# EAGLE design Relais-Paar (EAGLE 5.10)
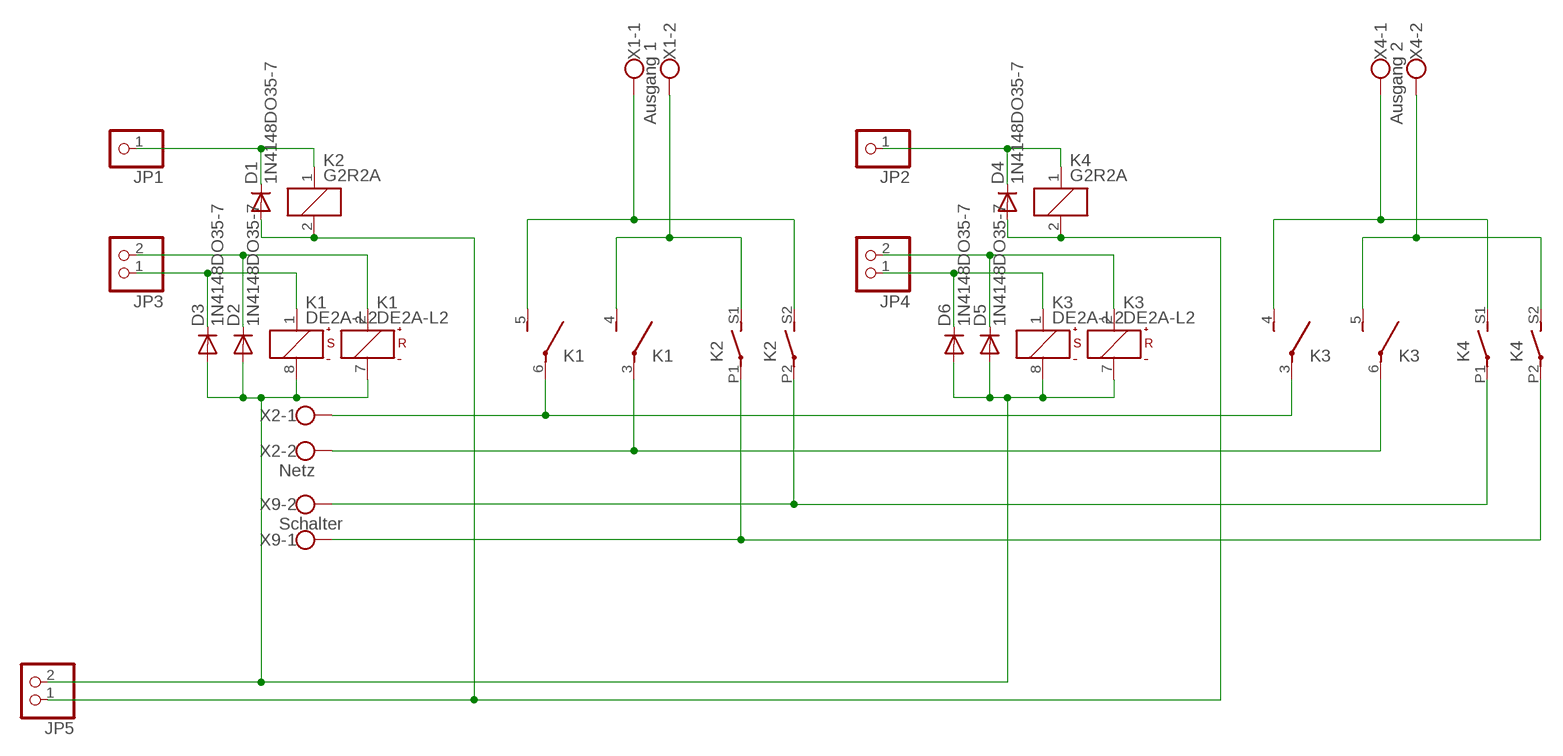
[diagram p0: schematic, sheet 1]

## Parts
D1  1N4148DO35-7  [DO35-7]
D2  1N4148DO35-7  [DO35-7]
D3  1N4148DO35-7  [DO35-7]
D4  1N4148DO35-7  [DO35-7]
D5  1N4148DO35-7  [DO35-7]
D6  1N4148DO35-7  [DO35-7]
JP1  PINHD-1X1  [1X01]
JP2  PINHD-1X1  [1X01]
JP3  PINHD-1X2  [1X02]
JP4  PINHD-1X2  [1X02]
JP5  PINHD-1X2  [1X02]
K1  DE2A-L2  [DE2A-L2]
K2  G2R2A  [G2R2A]
K3  DE2A-L2  [DE2A-L2]
K4  G2R2A  [G2R2A]
X1  Ausgang 1  W237-02P  [W237-132]
X2  Netz  W237-02P  [W237-132]
X4  Ausgang 2  W237-02P  [W237-132]
X9  Schalter  W237-02P  [W237-132]

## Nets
N$1 [mains]: K1.6(S2:P) K3.3(S1:P) X2.1
N$2 [mains]: K1.3(S1:P) K3.6(S2:P) X2.2
N$3 [mains]: K1.5(S2:S) K2.S2(3:S) X1.1
N$4 [mains]: K1.4(S1:S) K2.S1(2:S) X1.2
N$5 [mains]: K2.P1(2:P) K4.P2(3:P) X9.1
N$6 [mains]: K2.P2(3:P) K4.P1(2:P) X9.2
N$7: D2.A D3.A D5.A D6.A JP5.2 K1.7(R:-) K1.8(S:-) K3.7(R:-) K3.8(S:-)
N$8: D3.C JP3.1 K1.1(S:+)
N$9: D2.C JP3.2 K1.2(R:+)
N$10: D1.A D4.A JP5.1 K2.2 K4.2
N$11: D1.C JP1.1 K2.1
N$14 [mains]: K3.4(S1:S) K4.S1(2:S) X4.1
N$15 [mains]: K3.5(S2:S) K4.S2(3:S) X4.2
N$19: D6.C JP4.1 K3.1(S:+)
N$20: D5.C JP4.2 K3.2(R:+)
N$22: D4.C JP2.1 K4.1

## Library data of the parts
D1-D6 = diode:1N4148: DIODE
JP1 JP2 = pinhead:PINHD-1X1: PIN HEADER
JP3-JP5 = pinhead:PINHD-1X2: PIN HEADER
K1 K3 = 11my-mechanics:DE2A-L2*: MINIATURE RELAY NAiS DE2a-L2 Source: Pollin
K2 K4 = relay:G2R2A: RELAY 2 x norm. open, Omron
X1 X2 X4 X9 = con-wago-508:W237-02P: WAGO SREW CLAMP

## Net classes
1 mains: width 4 mm, clearance 2 mm

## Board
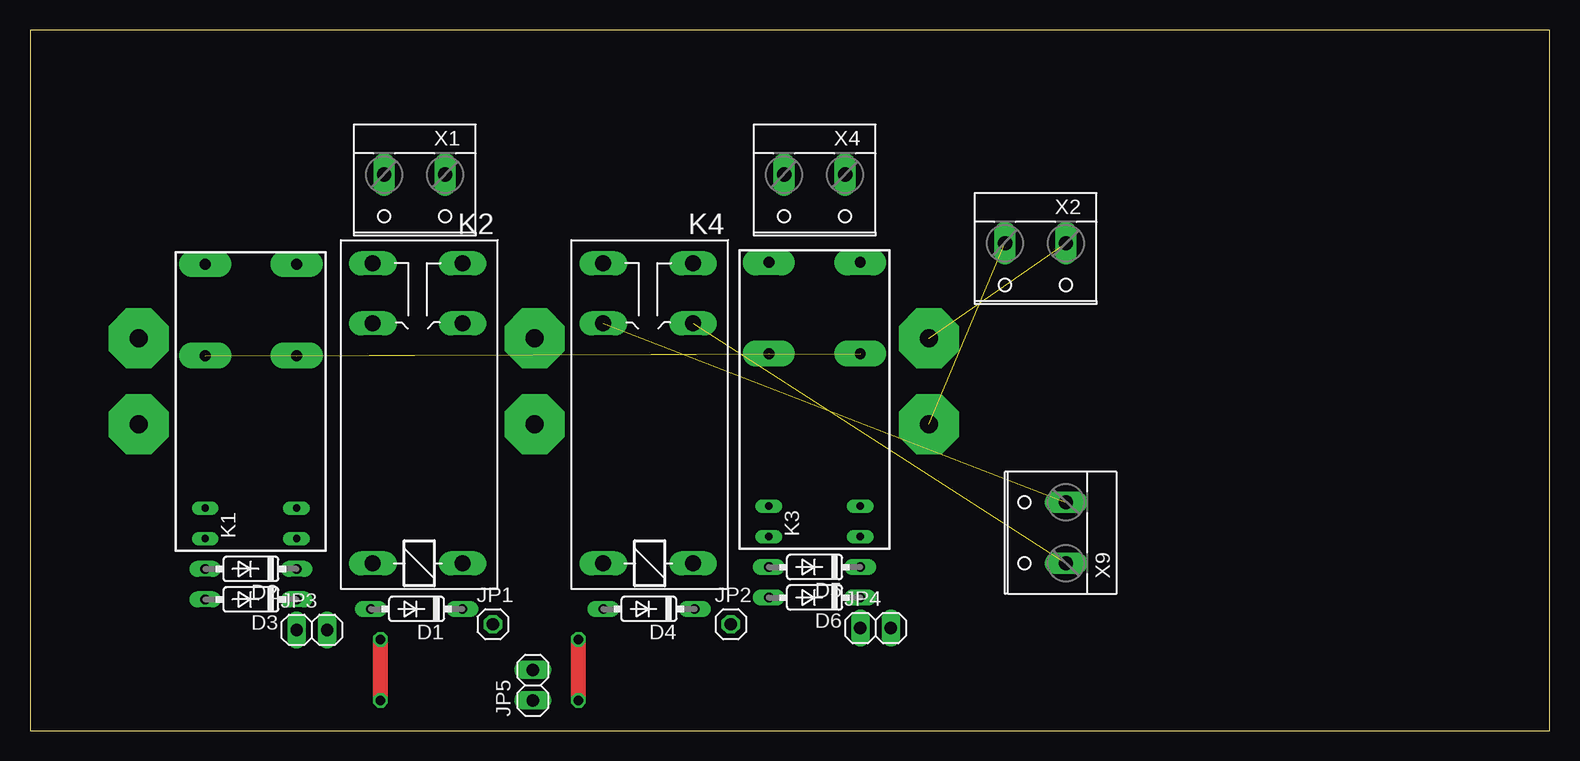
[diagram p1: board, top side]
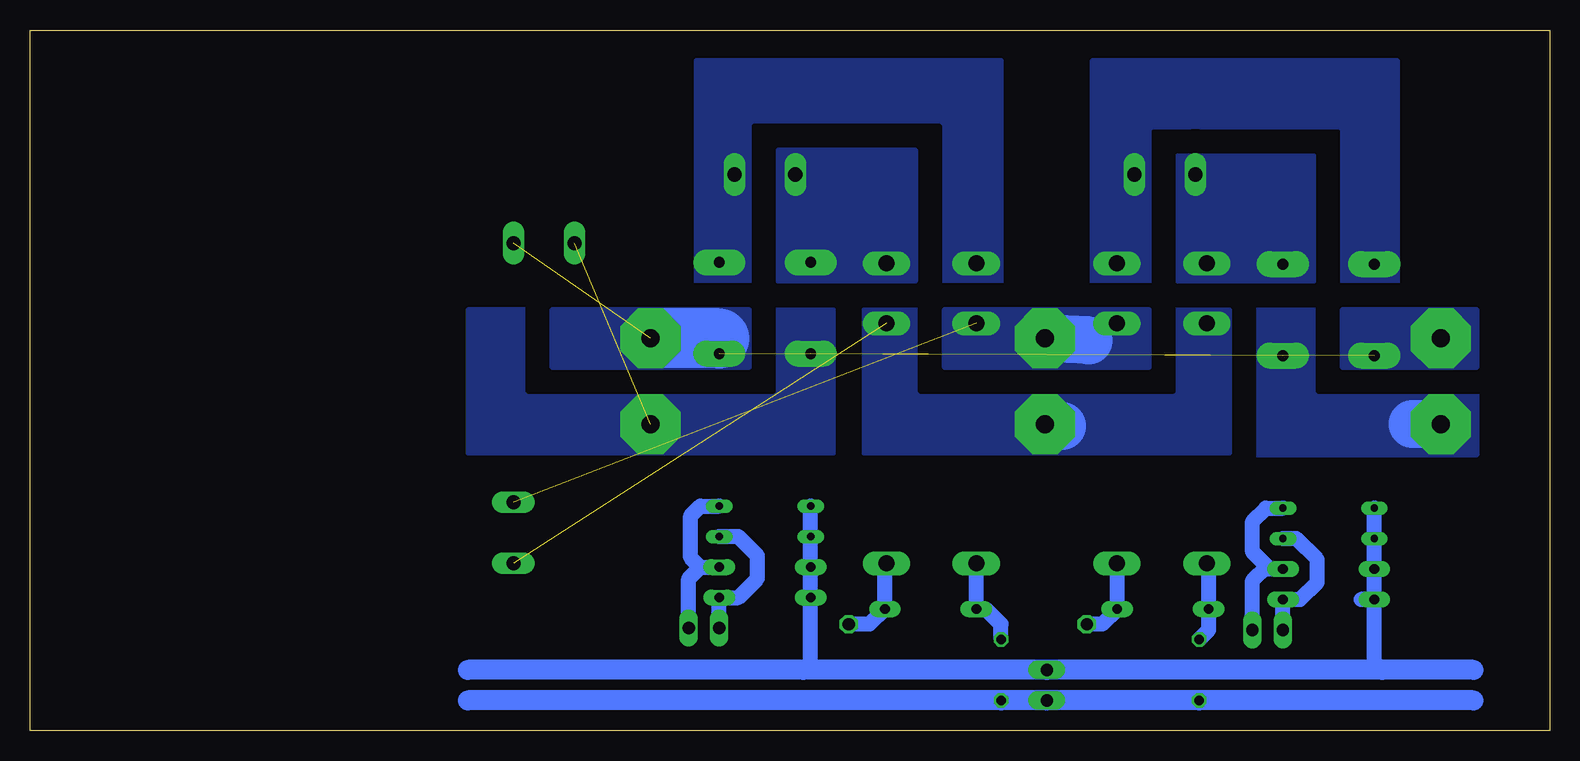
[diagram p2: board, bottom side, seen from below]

Size 126.67 x 58.41 mm. Coordinates in mm from the lower left corner, seen from the top.
Outline: 0,0 126.67,0 126.67,58.41 0,58.41 0,0
Copper layers (1*16): Top 0.035mm / dielectric 1.5mm / Bottom 0.035mm
Design rules "default": minimum track width 10mil, minimum drill 24mil, track to track 8mil, track to pad 8mil, pad to pad 8mil, via to via 8mil, smd to smd 8mil, copper to edge 40mil, drill to drill 8mil, minimum pad ring 10mil, minimum via ring 8mil, stop-mask expansion 4mil, vias tented up to drill 0mil, thermal gap 10mil

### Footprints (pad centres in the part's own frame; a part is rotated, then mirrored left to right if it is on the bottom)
DO35-7 = drill 0.813 long: A 3.81,0; C -3.81,0
1X01 = drill 1.016 octagon: 1 0,0
1X02 = drill 1.016 long: 1 -1.27,0; 2 1.27,0
DE2A-L2 = drill 0.61 long: 1 -8.89,-3.81; 2 -6.35,-3.81; 7 -6.35,3.81; 8 -8.89,3.81 | drill 0.9 pad 2.184 long: 3 6.35,-3.81; 4 13.97,-3.81; 5 13.97,3.81; 6 6.35,3.81
G2R2A = drill 1.321 long: 1 -2.54,-3.683; 2 -2.54,3.81; P1 17.45,3.81; P2 17.45,-3.683; S1 22.454,3.81; S2 22.454,-3.683
W237-132 = drill 1.194 long: 1 -2.54,-0.635; 2 2.54,-0.635

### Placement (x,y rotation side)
D1  32.23,10.16 180 top
D2  18.41,13.49 180 top
D3  18.41,10.95 180 top
D4  51.59,10.16 180 top
D5  65.41,13.65 180 top
D6  65.41,11.11 180 top
JP1  38.58,8.89 0 top
JP2  58.42,8.89 0 top
JP3  23.5,8.41 0 top
JP4  70.48,8.57 0 top
JP5  41.91,3.81 90 top
K1  18.41,24.92 90 top
K2  32.38,16.51 90 top
K3  65.41,25.08 90 top
K4  51.59,16.51 90 top
X1  32.07,45.72 180 top
X2  83.82,40.01 180 top
X4  65.41,45.72 180 top
X9  85.72,16.51 90 top

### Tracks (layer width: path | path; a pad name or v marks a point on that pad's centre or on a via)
N$1  (via drill 1.5 pad 5)  (2 unrouted)
  Bottom 5: 69.22,32.7 v74.93,32.7 | 69.22,32.7
  other vias: 9.05,32.7
  pour Bottom: 17.3,35.08 17.3,30.32 6.03,30.32 6.03,35.08
  pour Bottom (no thermals): 83.19,35.08 83.19,30.32 66.67,30.32 66.67,35.08
N$2  (via drill 1.5 pad 5)  (2 unrouted)
  Bottom 4: v9.05,25.56 11.43,25.56
  other vias: 74.93,25.56
  pour Bottom (isolate 2, rank 3): 24.61,35.08 24.61,23.02 6.03,23.02 6.03,35.08
  pour Bottom (isolate 2, rank 2, no thermals): 59.69,23.18 59.69,35.08 90.17,35.08 90.17,23.18
N$3
  pour Bottom (isolate 2, rank 4, no thermals): 12.7,36.83 38.1,36.83 38.1,55.88 12.7,55.88
N$4
  pour Bottom (no thermals): 19.69,47.94 19.69,37.47 30.96,37.47 30.96,47.94
N$5  (via drill 1.5 pad 5)  (1 unrouted)
  Bottom 4: v42.07,25.56 40.64,25.4
  pour Bottom (isolate 2, rank 2, no thermals): 26.67,23.18 26.67,35.08 57.15,35.08 57.15,23.18
N$6  (via drill 1.5 pad 5)  (1 unrouted)
  Bottom 4: 38.42,32.54 v42.07,32.7
  pour Bottom (no thermals): 50.48,35.08 50.48,30.32 33.34,30.32 33.34,35.08
N$7
  Bottom 1.27: K1.7 K1.8 D2.A D3.A | D3.A 15.72,10.95 | K3.8 K3.7 | D5.A D6.A 61.59,5.71 62.23,5.08 | D5.A | D5.A K3.8 | K3.8 | D3.A 14.61,5.71 13.97,5.08
  Bottom 1.676: 90.17,5.08 62.23,5.08 JP5.2 13.97,5.08 6.35,5.08
N$8
  Bottom 1.27: K1.1 | K1.1 21.11,16.03 19.37,14.29 19.37,12.38 20.8,10.95 D3.C | D3.C 21.59,10.95 | JP3.1 D3.C | D3.C
N$9
  Bottom 1.27: D2.C | D2.C 23.34,13.49 23.57,13.73 | 23.57,13.73 24.77,14.92 24.77,17.46 23.65,18.57 K1.2 | K1.2 | JP3.2 24.77,12.54 23.57,13.73
N$10  (via drill 0.8)
  Top 1.27: v45.72,2.54 v45.72,7.62 | v29.21,2.54 v29.21,7.62
  Bottom 1.27: K4.2 D4.A 46.99,10.16 45.72,8.89 v45.72,7.62 | K2.2 28.42,13.81 D1.A 28.42,8.41 v29.21,7.62
  Bottom 1.676: 90.17,2.54 v45.72,2.54 JP5.1 v29.21,2.54 6.35,2.54
N$11
  Bottom 1.27: K2.1 36.04,13.84 D1.C 37.31,8.89 JP1.1
N$14
  pour Bottom (isolate 2, rank 4, no thermals): 45.72,36.83 71.12,36.83 71.12,55.88 45.72,55.88
N$15
  pour Bottom (no thermals): 52.86,48.42 52.86,37.47 64.29,37.47 64.29,48.42
N$19
  Bottom 1.27: JP4.1 D6.C 67.63,11.11 66.04,12.7 66.04,14.61 67.63,16.19 K3.1
N$20
  Bottom 1.27: K3.2 70.8,18.73 71.6,17.94 71.6,14.45 70.8,13.65 | 70.8,13.65 D5.C | JP4.2 71.75,12.7 70.8,13.65
N$22
  Bottom 1.27: K4.1 55.4,13.84 D4.C 56.67,8.89 JP2.1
